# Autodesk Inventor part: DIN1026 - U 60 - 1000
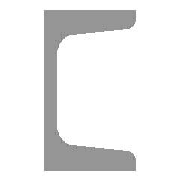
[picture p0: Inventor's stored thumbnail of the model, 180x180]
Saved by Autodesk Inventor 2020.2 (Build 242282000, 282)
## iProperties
Manager: www.cadconsulting.pl
Company: Fabian Stasiak CAD Consulting
IsCustomPart: 1
Created: 2014-02
Part Number: DIN1026 - U 60 - 1000
Material: Stal, miękka
Description: Ceownik
Document SubType Name: Modeling
Standard: DIN 1026
Designer: F.Stasiak
Standard Revision: 2000
Standards Organization: DIN
Language: pl-PL
Size Designation: U 60 - 1000
Categories: <MemberInstance><Categories><Category DisplayName="Kształtowniki konstrukcyjne" InternalName="089c4875-fa83-4c05-b084-43b9cc11f5ed" Mnemonic="GRDR"><CategoryPar
Stock Number: U 60
Density: 7.85 g/cm^3
Appearance: Częściowo polerowana
Catalog Web Link: www.expertbooks.pl
G_L: 1000,000 mm
Author: F.Stasiak
Subject: Zbiór ćwiczeń. Autodesk Inventor 2020. Kurs Professional
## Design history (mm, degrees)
node "Płaszczyzna początkowa"
node "Płaszczyzna końcowa"
sketch "Szkic"
  geometry: L1 (0, 0)-(0, 30); L2 (0, 30)-(30, 30); L3 (30, 30)-(30, 27.97); L4 (27.239, 24.979)-(11.522, 23.722); L5 (6, 17.741)-(6, 0); L6 (6, 0)-(0, 0); L7 (15, 30)-(15, 24); L8 (30, 25.2)-(30, 24); L9 (30, 24)-(15, 24); L10 (0, 15)-(0, -27); L11 (-5.539, 0)-(16.007, 0); L12 (0, 0)-(0, -30); L13 (0, -30)-(30, -30); L14 (30, -30)-(30, -27.97); L15 (27.239, -24.979)-(11.522, -23.722); L16 (6, -17.741)-(6, 0); L17 (0, 23.4)-(0, -35.4) reference; L18 (-9.848, 0)-(20.316, 0) reference; A1 r 6 centre (12, 17.741) between (11.522, 23.722) and (6, 17.741); A2 r 6 centre (12, -17.741) between (6, -17.741) and (11.522, -23.722); A3 r 3 centre (27, 27.97) between (27.239, 24.979) and (30, 27.97); A4 r 3 centre (27, -27.97) between (30, -27.97) and (27.239, -24.979); 5 further points
  constraints: 32 end point, 10 point on line, 8 point on circle, 8 tangent, 6 symmetric about line, 4 centre point, 4 parallel, 3 collinear, 3 perpendicular, 2 equal radius, 2 midpoint, 5 other
  dimensions: "d0" = 6 distance between parallel lines of L1 L5 (= G_T); "d1" = 30 distance between parallel lines of L6 L2 (= 0.5 x G_H); "d2" = 30 distance between parallel lines of L3 L1 (= G_W); "d3" = 6 distance of L2.end L8.end (= G_T1); "d4" = 15 distance of L7.start L2.end (= G_C); "d5" = 1.2 distance of L8.start L8.end (computed from G_NG, G_C); "d23" = 6 radius of A1 (= G_IR); "d24" = 3 radius of A3 (= G_ER); "d25" = 0 distance between parallel lines of L10 L12 (computed from ex)
extrude "Bryła" new body sketch "Szkic" stored distance "d6" = 1000 (= G_L); taper "d7" = 0 deg
node "Driven Length"
  sketch "Sketch3"
    geometry: L1 (0, 0)-(10, 0) reference
    constraints: 2 end point, 1 horizontal
  workplane "Work Plane3"
  sketch "Sketch4"
    geometry: L1 (-2, 0)-(12, 0) reference; L2 (-2, 1000)-(12, 1000) reference
    dimensions: "d29" = 1000 distance between parallel lines of L1 L2 (derived)
body "Solid1"
other parameters: "G_W" = 30 [user parameter; used in 1 equation term], "G_T" = 6 [user parameter; used in 1 equation term], "G_T1" = 6 [user parameter; used in 1 equation term], "G_NG" = 0.8 [user parameter; used in 1 equation term], "G_ER" = 3 [user parameter; used in 1 equation term], "G_IR" = 6 [user parameter; used in 1 equation term], "G_C" = 15 [user parameter; used in 2 equation terms], "G_L" = 1000 (= d29) [user parameter; used in 1 equation term], "ex" = 0 [user parameter; used in 1 equation term], "G_OFFSET_START" = 0 [user parameter; used in 1 equation term], "G_OFFSET_END" = 0 [user parameter; used in 1 equation term], "d26" = 0 (computed from G_OFFSET_START), "d28" = 90 deg
